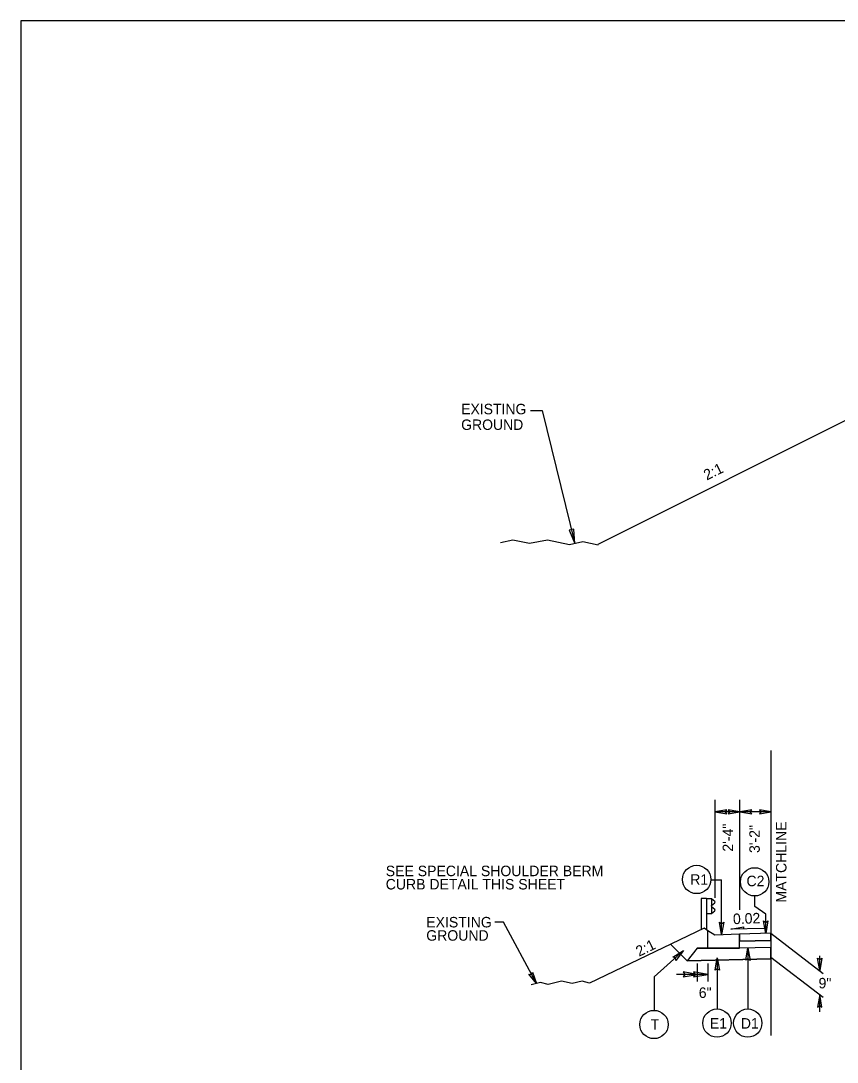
# Model space of a CAD drawing. Extents: x 574442 to 2463611, y -53527 to 675895.
# Drawn here: x 574441.8 to 574493.9, y -53471.4 to -53404.9 of the extents above; entities that cross this region are included whole.
import ezdxf

# ---------------------------------------------------------------- set-up
doc = ezdxf.new("R2010")
doc.units = 0
for name, color, linetype in [('Old_Level_1', 7, 'Continuous'), ('Old_Level_21', 7, 'Continuous'), ('Old_Level_22', 7, 'Continuous'), ('Old_Level_23', 7, 'Continuous'), ('Prop Shade Heavy', 7, 'Continuous'), ('Sheet Plot Border Outside CELL', 7, 'Continuous'), ('Typical Curb CELL', 7, 'Continuous'), ('Typical Guardrail CELL', 7, 'Continuous')]:
    doc.layers.add(name, color=color, linetype=linetype)

msp = doc.modelspace()

# ---------------------------------------------------------------- linework, layer by layer
at = {"layer": 'Old_Level_1'}
msp.add_line((574489.712, -53456.475), (574489.712, -53456.475), dxfattribs=at)
at = {"layer": 'Old_Level_22'}
for p, q in [((574474.375, -53429.776), (574475.11, -53429.776)), ((574475.11, -53429.776), (574477.196, -53438.263)), ((574478.69, -53438.312), (574495.356, -53429.978)), ((574489.712, -53451.48), (574489.712, -53469.679)), ((574485.45, -53462.833), (574478.148, -53466.339)), ((574485.688, -53462.995), (574485.45, -53462.833)), ((574489.712, -53463.161), (574487.712, -53463.213)), ((574484.371, -53464.924), (574483.308, -53463.861)), ((574489.712, -53463.613), (574487.712, -53463.665)), ((574485.018, -53464.116), (574484.371, -53464.924)), ((574485.018, -53464.116), (574484.371, -53464.924)), ((574485.018, -53464.116), (574485.688, -53464.116)), ((574485.688, -53464.116), (574485.018, -53464.116)), ((574487.712, -53464.116), (574485.688, -53464.116)), ((574489.712, -53464.064), (574487.712, -53464.116)), ((574489.712, -53464.064), (574487.712, -53464.116)), ((574489.712, -53464.786), (574489.712, -53464.064)), ((574489.712, -53464.786), (574484.371, -53464.924)), ((574484.371, -53464.924), (574489.712, -53464.786))]:
    msp.add_line(p, q, dxfattribs=at)
for points in [[(574472.449, -53438.2), (574473.233, -53438.03), (574474.3, -53438.243), (574475.458, -53438.03), (574476.861, -53438.335), (574477.714, -53438.152), (574478.69, -53438.365)], [(574478.148, -53466.339), (574477.679, -53466.212), (574477.041, -53466.371), (574476.348, -53466.212), (574475.509, -53466.44), (574474.999, -53466.303), (574474.415, -53466.462)]]:
    msp.add_lwpolyline(points, dxfattribs=at)
at = {"layer": 'Old_Level_23'}
for p, q in [((574486.149, -53454.63), (574486.149, -53460.888)), ((574487.712, -53454.63), (574487.712, -53461.662)), ((574487.741, -53455.402), (574486.149, -53455.402)), ((574489.741, -53455.402), (574487.741, -53455.402)), ((574485.883, -53459.756), (574486.574, -53459.756)), ((574486.574, -53463.249), (574486.574, -53459.756)), ((574488.696, -53461.448), (574488.696, -53460.78)), ((574489.395, -53461.946), (574488.696, -53461.448)), ((574472.637, -53462.443), (574472.089, -53462.443)), ((574474.75, -53466.371), (574472.637, -53462.443)), ((574489.395, -53463.169), (574489.395, -53461.946)), ((574489.275, -53462.859), (574487.165, -53462.899)), ((574489.712, -53463.161), (574493.057, -53465.721)), ((574484.138, -53464.251), (574482.259, -53465.951)), ((574488.254, -53464.09), (574488.254, -53467.994)), ((574492.834, -53465.54), (574492.834, -53464.593)), ((574485.018, -53465.085), (574485.018, -53466.243)), ((574485.688, -53465.085), (574485.688, -53466.243)), ((574486.291, -53464.724), (574486.291, -53467.994)), ((574489.712, -53464.687), (574493.057, -53467.246)), ((574485.018, -53465.792), (574483.7, -53465.792)), ((574485.688, -53465.792), (574484.37, -53465.792)), ((574482.259, -53465.951), (574482.259, -53468.082)), ((574492.834, -53468.182), (574492.834, -53467.076))]:
    msp.add_line(p, q, dxfattribs=at)
for points in [[(574477.196, -53438.263), (574477.131, -53437.357), (574476.841, -53437.427)], [(574486.902, -53455.272), (574486.149, -53455.402), (574486.907, -53455.536), (574486.81, -53455.402)], [(574486.987, -53455.532), (574487.741, -53455.402), (574486.983, -53455.268), (574487.08, -53455.402)], [(574488.495, -53455.272), (574487.741, -53455.402), (574488.499, -53455.536), (574488.403, -53455.402)], [(574488.987, -53455.532), (574489.741, -53455.402), (574488.983, -53455.268), (574489.08, -53455.402)], [(574486.711, -53462.453), (574486.574, -53463.249), (574486.433, -53462.448), (574486.574, -53462.55)], [(574489.532, -53462.373), (574489.395, -53463.169), (574489.253, -53462.369), (574489.395, -53462.47)], [(574487.165, -53462.899), (574487.966, -53462.75), (574487.968, -53462.884)], [(574483.455, -53464.683), (574484.138, -53464.251), (574483.639, -53464.893), (574483.619, -53464.72)], [(574488.117, -53464.886), (574488.254, -53464.09), (574488.396, -53464.89), (574488.254, -53464.788)], [(574486.154, -53465.521), (574486.291, -53464.724), (574486.432, -53465.525), (574486.291, -53465.423)], [(574492.971, -53464.744), (574492.834, -53465.54), (574492.693, -53464.74), (574492.834, -53464.842)], [(574474.507, -53465.646), (574474.75, -53466.371), (574474.273, -53465.767), (574474.437, -53465.788)], [(574484.114, -53465.948), (574485.018, -53465.792), (574484.109, -53465.631), (574484.224, -53465.792)], [(574484.784, -53465.948), (574485.688, -53465.792), (574484.779, -53465.631), (574484.894, -53465.792)], [(574492.971, -53467.872), (574492.834, -53467.076), (574492.693, -53467.877), (574492.834, -53467.775)]]:
    msp.add_lwpolyline(points, close=True, dxfattribs=at)
for centre in [(574484.979, -53459.726), (574488.683, -53459.876), (574482.253, -53468.986), (574486.279, -53468.899), (574488.242, -53468.899)]:
    msp.add_circle(centre, 0.904, dxfattribs=at)
at = {"layer": 'Prop Shade Heavy'}
for p, q in [((574489.712, -53463.161), (574487.712, -53463.213)), ((574487.712, -53463.213), (574487.712, -53463.665)), ((574489.712, -53463.613), (574489.712, -53463.161)), ((574487.712, -53463.665), (574489.712, -53463.613))]:
    msp.add_line(p, q, dxfattribs=at)
at = {"layer": 'Sheet Plot Border Outside CELL'}
msp.add_lwpolyline([(574441.833, -53527.117), (574628.889, -53527.117), (574628.889, -53404.895), (574441.833, -53404.895)], close=True, dxfattribs=at)
at = {"layer": 'Typical Curb CELL'}
for p, q in [((574485.688, -53464.116), (574485.688, -53462.995)), ((574486.149, -53463.283), (574485.688, -53462.995)), ((574487.712, -53463.213), (574486.149, -53463.283)), ((574487.712, -53464.116), (574487.712, -53463.213)), ((574485.688, -53464.116), (574487.712, -53464.116))]:
    msp.add_line(p, q, dxfattribs=at)
at = {"layer": 'Typical Guardrail CELL'}
for p, q in [((574485.602, -53460.936), (574485.269, -53460.936)), ((574485.269, -53460.936), (574485.269, -53462.92)), ((574485.602, -53460.936), (574485.602, -53462.936)), ((574485.602, -53460.936), (574485.935, -53460.936)), ((574485.935, -53460.936), (574485.935, -53461.907)), ((574485.935, -53460.936), (574486.129, -53461.106)), ((574485.935, -53461.382), (574486.129, -53461.212)), ((574485.602, -53461.907), (574485.935, -53461.907)), ((574485.935, -53461.421), (574485.935, -53461.382)), ((574485.935, -53461.421), (574485.935, -53461.46)), ((574485.935, -53461.46), (574486.129, -53461.63)), ((574485.935, -53461.907), (574486.129, -53461.737))]:
    msp.add_line(p, q, dxfattribs=at)
for centre, major_axis, start_param, end_param in [((574486.099, -53461.159), (0, -0.065), 0.61067, 2.530675), ((574486.099, -53461.684), (0, 0.065), 3.751819, 5.672217)]:
    msp.add_ellipse(centre, major_axis=major_axis, ratio=0.8, start_param=start_param, end_param=end_param, dxfattribs=at)

# ---------------------------------------------------------------- texts
at = {"layer": 'Old_Level_21'}
for s, p in [('EXISTING', (574469.946, -53430.019)), ('GROUND', (574469.946, -53431.019))]:
    msp.add_text(s, height=0.6667, dxfattribs=at).set_placement(p)
for p in [(574485.626, -53434.249), (574481.299, -53464.668)]:
    msp.add_text('2:1', height=0.6733, rotation=26.03624, dxfattribs=at).set_placement(p)
at = {"layer": 'Old_Level_23'}
for s, rotation, p in [('2\'-4"', 90, (574487.307, -53457.947)), ('3\'-2"', 90, (574489.01, -53458.034)), ('MATCHLINE', 90, (574490.714, -53461.2)), ('0.02', 2, (574487.308, -53462.581))]:
    msp.add_text(s, height=0.67, rotation=rotation, dxfattribs=at).set_placement(p)
for s, p in [('SEE SPECIAL SHOULDER BERM', (574465.129, -53459.515)), ('CURB DETAIL THIS SHEET', (574465.129, -53460.364)), ('R1', (574484.567, -53460.061)), ('C2', (574488.159, -53460.156)), ('EXISTING', (574467.716, -53462.786)), ('GROUND', (574467.716, -53463.635)), ('9"', (574492.761, -53466.68)), ('6"', (574485.113, -53467.288)), ('E1', (574485.815, -53469.25)), ('D1', (574487.8, -53469.25)), ('T', (574482.037, -53469.326))]:
    msp.add_text(s, height=0.67, dxfattribs=at).set_placement(p)

doc.saveas('drawing.dxf')
